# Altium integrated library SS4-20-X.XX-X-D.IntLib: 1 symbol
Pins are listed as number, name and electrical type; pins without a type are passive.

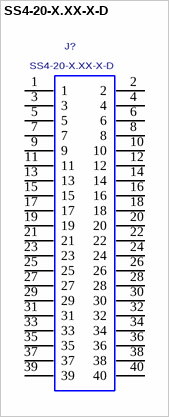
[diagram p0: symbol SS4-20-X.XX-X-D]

## SS4-20-X.XX-X-D
designator J?
0.4MM SOCKET STRIP ASSEMBLY, 40 PINS.; MANUFACTURER: SAMTEC
footprint SS4-20-X.XX-X-D
pins: 1, 2, 3, 4, 5, 6, 7, 8, 9, 10, 11, 12, 13, 14, 15, 16, 17, 18, 19, 20, 21, 22, 23, 24, 25, 26, 27, 28, 29, 30, 31, 32, 33, 34, 35, 36, 37, 38, 39, 40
